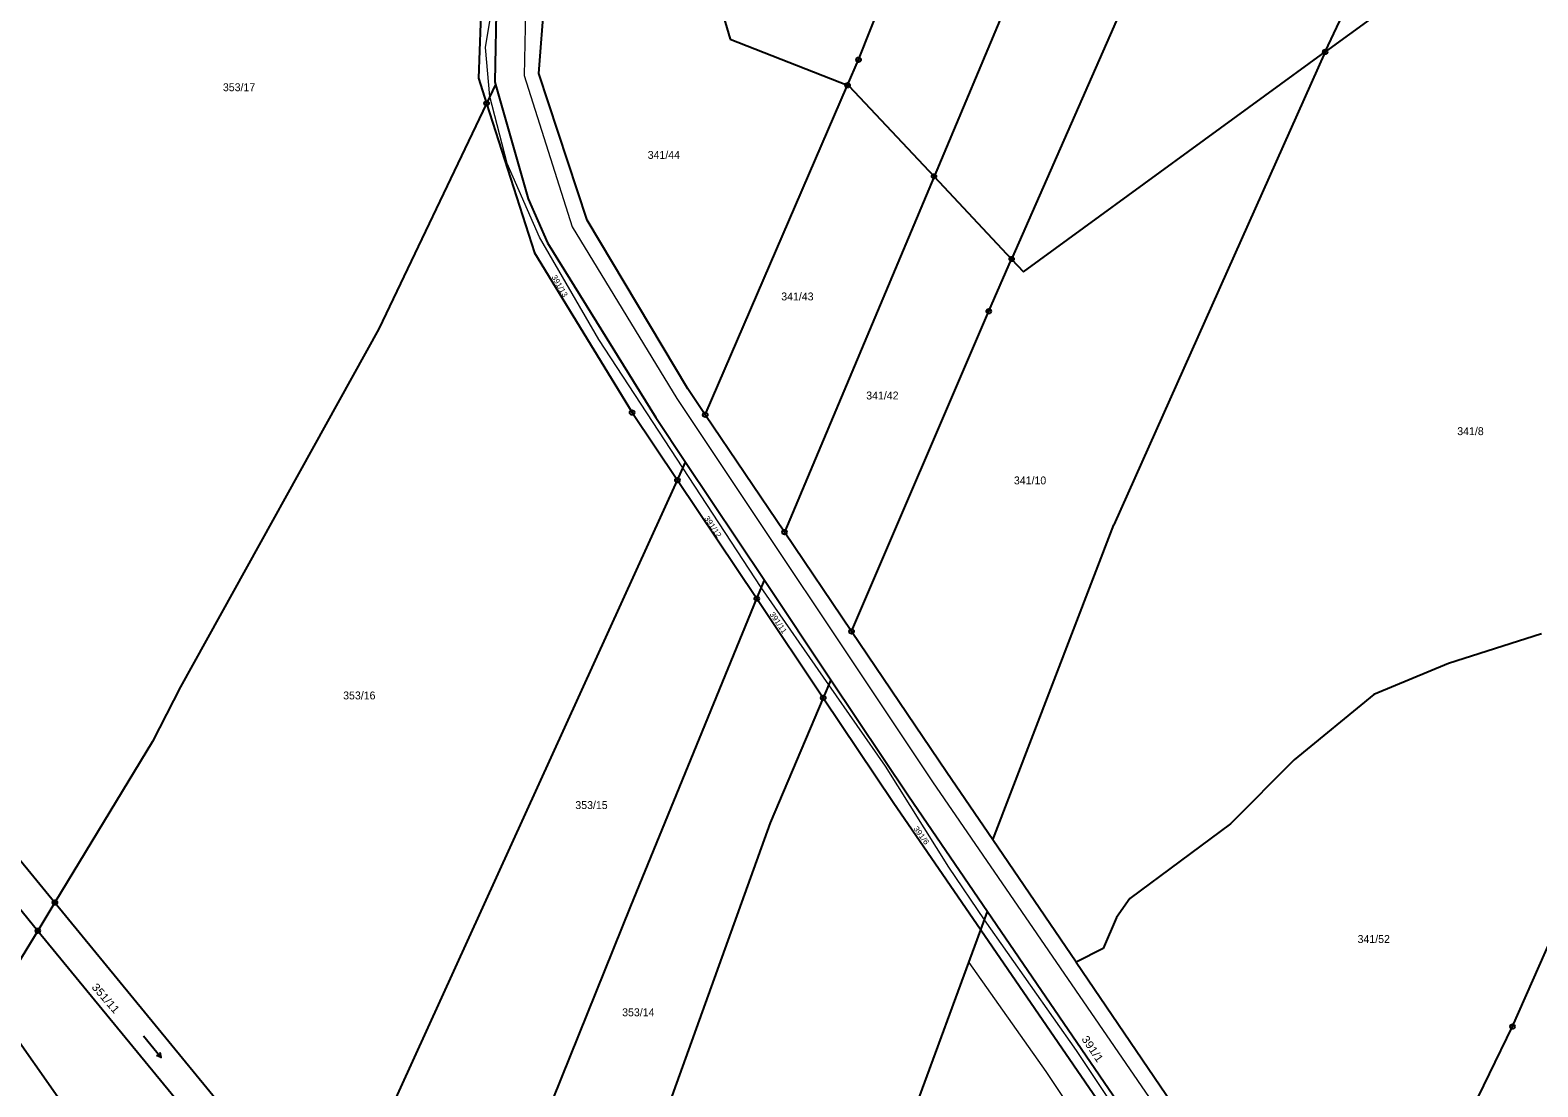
# Model space of a CAD drawing. Extents: x -504006 to -501322, y -1128098 to -1124665.
# Drawn here: x -502552.5 to -502227.9, y -1127389.9 to -1127162.4 of the extents above; entities that cross this region are included whole.
import ezdxf
from ezdxf.enums import TextEntityAlignment as Align

# ---------------------------------------------------------------- set-up
doc = ezdxf.new("R2010")
doc.units = 0
doc.header["$LTSCALE"] = 0.68
for name, color, linetype, lineweight in [('1', 7, 'Continuous', 25), ('13', 7, 'Continuous', 13), ('3', 7, 'Continuous', 25), ('4', 7, 'Continuous', 13), ('8', 7, 'Continuous', 25)]:
    doc.layers.add(name, color=color, linetype=linetype, lineweight=lineweight)
doc.layers.add('2', color=7, linetype='Continuous')

msp = doc.modelspace()

# ---------------------------------------------------------------- linework, layer by layer
at = {"layer": '1'}
for p, q in [((-502311.55, -1127083.65), (-502357.89, -1127193.86)), ((-502374.12, -1127168.75), (-502346.64, -1127099)), ((-502273.66, -1127167.07), (-502242.92, -1127101.61)), ((-502412.56, -1127128.07), (-502401.75, -1127164.32)), ((-502229.92, -1127135.18), (-502273.66, -1127167.07)), ((-502310.1, -1127140.83), (-502341.17, -1127211.66)), ((-502455.08, -1127147.67), (-502455.97, -1127172.73)), ((-502452, -1127147.59), (-502452.47, -1127173.47)), ((-502442.95, -1127171.7), (-502441.78, -1127155.83)), ((-502401.75, -1127164.32), (-502376.49, -1127174.25)), ((-502376.49, -1127174.25), (-502374.12, -1127168.75)), ((-502338.59, -1127214.41), (-502273.66, -1127167.07)), ((-502273.66, -1127167.07), (-502319.15, -1127268.91)), ((-502432.59, -1127203.27), (-502442.95, -1127171.7)), ((-502455.97, -1127172.73), (-502454.24, -1127178.14)), ((-502452.3, -1127174.08), (-502454.24, -1127178.14)), ((-502452.47, -1127173.47), (-502452.3, -1127174.08)), ((-502452.3, -1127174.08), (-502445.25, -1127198.72)), ((-502407.14, -1127245.21), (-502376.49, -1127174.25)), ((-502376.49, -1127174.25), (-502376.2, -1127174.36)), ((-502376.2, -1127174.36), (-502357.89, -1127193.86)), ((-502454.24, -1127178.14), (-502477.42, -1127226.67)), ((-502454.24, -1127178.14), (-502443.95, -1127210.36)), ((-502357.89, -1127193.86), (-502390.09, -1127270.46)), ((-502357.89, -1127193.86), (-502341.17, -1127211.66)), ((-502445.25, -1127198.72), (-502441.13, -1127208.16)), ((-502410.93, -1127239.6), (-502432.59, -1127203.27)), ((-502443.95, -1127210.36), (-502422.91, -1127244.72)), ((-502441.13, -1127208.16), (-502417.8, -1127245.78)), ((-502346.1, -1127222.91), (-502341.17, -1127211.66)), ((-502341.17, -1127211.66), (-502338.59, -1127214.41)), ((-502375.64, -1127291.85), (-502346.1, -1127222.91)), ((-502477.42, -1127226.67), (-502520.17, -1127303.8)), ((-502407.14, -1127245.21), (-502410.93, -1127239.6)), ((-502422.91, -1127244.72), (-502413.15, -1127259.28)), ((-502417.8, -1127245.78), (-502411.38, -1127255.39)), ((-502390.09, -1127270.46), (-502407.14, -1127245.21)), ((-502413.15, -1127259.28), (-502411.38, -1127255.39)), ((-502411.38, -1127255.39), (-502394.41, -1127280.79)), ((-502477.45, -1127400.38), (-502413.15, -1127259.28)), ((-502413.15, -1127259.28), (-502396.05, -1127284.8)), ((-502345.22, -1127336.76), (-502319.15, -1127268.91)), ((-502375.64, -1127291.85), (-502390.09, -1127270.46)), ((-502396.05, -1127284.8), (-502394.41, -1127280.79)), ((-502394.41, -1127280.79), (-502380.08, -1127302.25)), ((-502423.2, -1127351.05), (-502396.05, -1127284.8)), ((-502396.05, -1127284.8), (-502381.73, -1127306.16)), ((-502355.13, -1127322.22), (-502375.64, -1127291.85)), ((-502227.11, -1127292.39), (-502247.11, -1127298.74)), ((-502233.32, -1127376.94), (-502196.85, -1127294.19)), ((-502590.93, -1127296.95), (-502547.19, -1127350.24)), ((-502247.11, -1127298.74), (-502263.15, -1127305.41)), ((-502596.54, -1127300.64), (-502550.86, -1127356.3)), ((-502520.17, -1127303.8), (-502526.17, -1127315.57)), ((-502380.08, -1127302.25), (-502381.73, -1127306.16)), ((-502380.08, -1127302.25), (-502363.38, -1127327.24)), ((-502381.73, -1127306.16), (-502393.17, -1127333.08)), ((-502381.73, -1127306.16), (-502366.68, -1127328.62)), ((-502263.15, -1127305.41), (-502280.35, -1127319.53)), ((-502526.17, -1127315.57), (-502547.19, -1127350.24)), ((-502280.35, -1127319.53), (-502294.04, -1127333.28)), ((-502345.22, -1127336.76), (-502355.13, -1127322.22)), ((-502363.38, -1127327.24), (-502346.35, -1127352.16)), ((-502366.68, -1127328.62), (-502347.81, -1127356.12)), ((-502393.17, -1127333.08), (-502423.69, -1127417.88)), ((-502294.04, -1127333.28), (-502315.71, -1127349.34)), ((-502327.31, -1127363.05), (-502345.22, -1127336.76)), ((-502547.19, -1127350.24), (-502550.86, -1127356.3)), ((-502547.19, -1127350.24), (-502487.71, -1127422.71)), ((-502315.71, -1127349.34), (-502318.63, -1127353.48)), ((-502445.78, -1127407.16), (-502423.2, -1127351.05)), ((-502347.81, -1127356.12), (-502346.35, -1127352.16)), ((-502346.35, -1127352.16), (-502274.05, -1127457.95)), ((-502318.63, -1127353.48), (-502321.44, -1127360.14)), ((-502550.86, -1127356.3), (-502556.01, -1127364.8)), ((-502550.86, -1127356.3), (-502490.81, -1127429.46)), ((-502374.42, -1127428.48), (-502347.81, -1127356.12)), ((-502347.81, -1127356.12), (-502275.69, -1127461.19)), ((-502321.44, -1127360.14), (-502327.31, -1127363.05)), ((-502327.31, -1127363.05), (-502268.61, -1127449.21)), ((-502562.12, -1127369.93), (-502543.51, -1127396.35)), ((-502268.61, -1127449.21), (-502233.32, -1127376.94))]:
    msp.add_line(p, q, dxfattribs=at)
at = {"layer": '13'}
msp.add_lwpolyline([(-502455.08, -1127147.67), (-502455.97, -1127172.73), (-502454.24, -1127178.14), (-502443.95, -1127210.36), (-502422.91, -1127244.72), (-502413.15, -1127259.28), (-502396.05, -1127284.8), (-502381.73, -1127306.16), (-502366.68, -1127328.62), (-502347.81, -1127356.12), (-502347.01, -1127353.95), (-502354.73, -1127342.64), (-502368.32, -1127320.9), (-502380.54, -1127303.34), (-502395.08, -1127282.42), (-502411.95, -1127256.65), (-502430.05, -1127229.02), (-502442.83, -1127206.94), (-502449.8, -1127191.11), (-502453.53, -1127176.66), (-502454.46, -1127166.14), (-502452.08, -1127151.78)], dxfattribs=at)
msp.add_lwpolyline([(-502294.17, -1127430.16), (-502311.08, -1127406.26), (-502327.23, -1127382.09), (-502347.01, -1127353.95), (-502347.81, -1127356.12), (-502350.39, -1127363.12), (-502333.83, -1127386.61), (-502317.68, -1127410.8), (-502300.77, -1127434.7), (-502278.76, -1127467.28), (-502269.56, -1127480.53), (-502252, -1127504.92), (-502249.08, -1127499.41), (-502247.82, -1127497.04), (-502263.02, -1127475.91), (-502274.66, -1127459.15)], close=True, dxfattribs=at)
at = {"layer": '3'}
msp.add_line((-502524.308, -1127383.61), (-502525.313, -1127383.166), dxfattribs=at)
msp.add_lwpolyline([(-502528.084, -1127378.947), (-502524.308, -1127383.61), (-502524.533, -1127382.535)], dxfattribs=at)
at = {"layer": '4'}
for p, q in [((-502413.25, -1127241.73), (-502358.23, -1127324.28)), ((-502358.23, -1127324.28), (-502252.53, -1127478))]:
    msp.add_line(p, q, dxfattribs=at)
msp.add_lwpolyline([(-502426.8, -1126972.66), (-502414.6, -1126984.27), (-502411.76, -1127006.91), (-502437.68, -1127105.38), (-502445.66, -1127147.93), (-502446.15, -1127172.16), (-502435.84, -1127204.7), (-502413.25, -1127241.73)], dxfattribs=at)
at = {"layer": '8'}
for centre, radius in [((-502374.12, -1127168.7499), 0.5), ((-502374.12, -1127168.7499), 0.0303), ((-502273.66, -1127167.0699), 0.5), ((-502273.66, -1127167.0699), 0.0303), ((-502376.49, -1127174.2499), 0.5), ((-502376.49, -1127174.2499), 0.0303), ((-502454.24, -1127178.1399), 0.5), ((-502454.24, -1127178.1399), 0.0303), ((-502357.89, -1127193.8599), 0.5), ((-502357.89, -1127193.8599), 0.0303), ((-502341.17, -1127211.6599), 0.5), ((-502341.17, -1127211.6599), 0.0303), ((-502346.1, -1127222.9099), 0.5), ((-502346.1, -1127222.9099), 0.0303), ((-502422.91, -1127244.7199), 0.5), ((-502422.91, -1127244.7199), 0.0303), ((-502407.14, -1127245.2099), 0.5), ((-502407.14, -1127245.2099), 0.0303), ((-502413.15, -1127259.2799), 0.5), ((-502413.15, -1127259.2799), 0.0303), ((-502390.09, -1127270.4599), 0.5), ((-502390.09, -1127270.4599), 0.0303), ((-502396.05, -1127284.7999), 0.5), ((-502396.05, -1127284.7999), 0.0303), ((-502375.64, -1127291.8499), 0.5), ((-502375.64, -1127291.8499), 0.0303), ((-502381.73, -1127306.1599), 0.5), ((-502381.73, -1127306.1599), 0.0303), ((-502547.19, -1127350.2399), 0.5), ((-502547.19, -1127350.2399), 0.0303), ((-502550.86, -1127356.2999), 0.5), ((-502550.86, -1127356.2999), 0.0303), ((-502233.32, -1127376.9399), 0.5), ((-502233.32, -1127376.9399), 0.0303)]:
    msp.add_circle(centre, radius, dxfattribs=at)

# ---------------------------------------------------------------- texts
at = {"layer": '2'}
for s, p in [('353/17', (-502511.01, -1127175.525)), ('341/44', (-502419.54, -1127190.095)), ('341/43', (-502390.78, -1127220.575)), ('341/42', (-502372.48, -1127241.905)), ('341/10', (-502340.68, -1127260.185)), ('353/16', (-502485.12, -1127306.495)), ('353/15', (-502435.12, -1127330.105)), ('353/14', (-502425.04, -1127374.725))]:
    msp.add_text(s, height=1.7, dxfattribs=at).set_placement(p)
for s, height, rotation, width, p in [('391/13', 1.2, 300, 1.05, (-502440.279, -1127215.52)), ('391/12', 1.2, 304, 1.05, (-502407.428, -1127267.507)), ('391/11', 1.2, 304, 1.05, (-502393.348, -1127288.177)), ('391/6', 1.2, 306, 1.1, (-502362.392, -1127334.336)), ('351/11', 1.7, 311, 1.1, (-502539.39, -1127368.528))]:
    msp.add_text(s, height=height, rotation=rotation, dxfattribs=dict(at, width=width)).set_placement(p)
for s, p in [('341/8', (-502242.37, -1127249.585)), ('341/52', (-502263.2, -1127358.945))]:
    msp.add_text(s, height=1.7, dxfattribs=at).set_placement(p, align=Align.CENTER)
at = {"layer": '2', "width": 1.1}
msp.add_text('391/1', height=1.7, rotation=304, dxfattribs=at).set_placement((-502324.4689, -1127382.2192), align=Align.CENTER)

doc.saveas('drawing.dxf')
